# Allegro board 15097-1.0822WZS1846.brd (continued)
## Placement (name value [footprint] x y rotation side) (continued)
R183  -  [0R0402-PAD]  58.24 144.93 90 top
R184  100KR2J-1-GP  [R402H16]  60.24 144.93 90 top
R185  10KR2J-3-GP  [R402H16]  163.33 140.95 0 top
R186  10R2F-L-GP  [R402H14]  160.84 139.06 180 top
R187  0R2J-2-GP  [R402H16]  45.58 137.82 0 top
R188  0R2J-2-GP  [R402H16]  46.62 137.82 0 top
R189  0R2J-2-GP  [R402H16]  47.76 137.82 0 top
R190  0R2J-2-GP  [R402H16]  48.8 137.82 0 top
R191  10R2F-L-GP  [R402H14]  160.85 136.83 180 top
R192  10R2F-L-GP  [R402H14]  160.85 134.89 0 top
R193  NTC-100K-8-GP  [NTC-603H38]  101.98 134.58 270 top
R194  10KR2J-3-GP  [R402H16]  100.1 132.76 90 top
R195  0R0402-PAD-1-GP  [0R0402-PAD]  160.86 132.88 0 top
R196  100KR2J-1-GP  [R402H16]  161.96 130.86 0 top
R197  0R2J-2-GP  [R402H16]  79.51 130.91 270 top
R198  0R0402-PAD-1-GP  [0R0402-PAD]  148.52 130.78 90 top
R199  0R2J-2-GP  [R402H16]  76.69 130.35 90 top
R200  100KR2J-1-GP  [R402H16]  159.82 131.75 180 top
R201  33R2J-2-GP  [R402H16]  88.63 128.62 90 top
R202  0R2J-2-GP  [R402H16]  76.66 129.31 90 top
R203  0R0402-PAD-2-GP  [0R0402-PAD-1]  148.12 129.11 270 top
R204  10KR2J-3-GP  [R402H16]  88.65 127.57 90 top
R205  0R0402-PAD-1-GP  [0R0402-PAD]  152.03 128.65 90 top
R206  0R2J-2-GP  [R402H16]  76.64 128.24 270 top
R207  33R2J-2-GP  [R402H16]  88.65 126.54 90 top
R208  0R2J-2-GP  [R402H16]  76.64 127.03 270 top
R209  10KR2J-3-GP  [R402H16]  88.65 125.47 90 top
R210  10KR2J-3-GP  [R402H16]  81.95 124.33 270 top
R211  10KR2J-3-GP  [R402H16]  76.31 124.26 180 top
R212  0R0402-PAD-2-GP  [0R0402-PAD-1]  88.59 123.08 90 top
R213  20KR2J-L2-GP  [R402H16]  144.16 119.75 0 top
R214  1KR2J-1-GP  [R402H16]  145.46 122.09 0 top
R215  10KR2J-3-GP  [R402H16]  75.6 121.87 0 top
R216  1KR2J-1-GP  [R402H16]  147.03 121.66 270 top
R217  10KR2J-3-GP  [R402H16]  84.89 120.52 0 top
R218  0R0402-PAD-2-GP  [0R0402-PAD-1]  125.64 119.53 180 top
R219  10KR2J-3-GP  [R402H16]  88.53 120.22 90 top
R220  8K2R2J-3-GP  [R402H16]  115.43 120.35 90 top
R221  0R0402-PAD-1-GP  [0R0402-PAD]  140.5 120.35 270 top
R222  1KR2J-1-GP  [R402H16]  96.65 119.08 90 top
R223  10KR2J-3-GP  [R402H16]  77.96 118.67 0 top
R224  0R2J-2-GP  [R402H16]  37.16 118.13 90 top
R225  0R0402-PAD-2-GP  [0R0402-PAD-1]  142.34 117.66 270 top
R226  8K2R2J-3-GP  [R402H16]  122.26 116.77 270 top
R227  10KR2J-3-GP  [R402H16]  139.67 117.25 180 top
R228  20KR2J-L2-GP  [R402H16]  140.75 117.23 180 top
R229  100KR2J-1-GP  [R402H16]  143.86 117.22 0 top
R230  0R0402-PAD-2-GP  [0R0402-PAD-1]  34.21 117.07 270 top
R231  0R2J-2-GP  [R402H16]  36.27 117.07 90 top
R232  10KR2J-3-GP  [R402H16]  99.94 116.33 0 top
R233  0R0402-PAD-1-GP  [0R0402-PAD]  40.48 116.08 90 top
R234  0R0402-PAD-2-GP  [0R0402-PAD-1]  132.35 115.99 0 top
R235  0R0402-PAD-2-GP  [0R0402-PAD-1]  133.39 115.99 0 top
R236  -  [0R0402-PAD]  34.65 114.99 90 top
R237  0R3J-0-U-GP  [R603H22]  127.01 115.5 90 top
R238  1KR2J-1-GP  [R402H16]  146.22 115.38 180 top
R239  10KR2J-3-GP  [R402H16]  94.8 114.83 90 top
R240  10KR2J-3-GP  [R402H16]  81.69 114.81 0 top
R241  10KR2J-3-GP  [R402H16]  83.65 114.81 0 top
R244  0R0402-PAD-1-GP  [0R0402-PAD]  42.82 114.59 180 top
R245  100KR2J-1-GP  [R402H16]  37.3 114.4 270 top
R246  200R2F-L-GP  [R402H16]  77.69 114.05 90 top
R247  2K49R2F-GP  [R402H16]  75.59 114.02 90 top
R248  0R2J-2-GP  [R402H16]  97.9 113.54 270 top
R250  0R2J-2-GP  [R402H16]  121.83 115.52 90 top
R251  0R3J-0-U-GP  [R603H22]  139.76 111.48 180 top
R252  10KR2F-2-GP  [R402H16]  127.39 111.1 270 top
R253  4K99R2F-L-GP  [R402H16]  47.65 111.07 0 top
R254  4K99R2F-L-GP  [R402H16]  48.67 111.07 180 top
R255  10KR2J-3-GP  [R402H16]  97.57 111 270 top
R256  0R0402-PAD-2-GP  [0R0402-PAD-1]  125.33 110.67 0 top
R257  80D6R2F-L-GP  [R402H16]  47.29 109.62 270 top
R258  243R2F-2-GP  [R402H16]  63.7 109.32 90 top
R259  162R2F-GP  [R402H16]  48.8 109.11 180 top
R260  1KR2J-1-GP  [R402H16]  99.45 108.74 90 top
R261  80D6R2F-L-GP  [R402H16]  47.29 108.61 270 top
R262  10KR2J-3-GP  [R402H16]  97.51 108.45 270 top
R263  0R0402-PAD-2-GP  [0R0402-PAD-1]  160.14 108.27 180 top
R264  40D2R2F-GP  [R402H16]  138.47 108.15 270 top
R265  0R0402-PAD-2-GP  [0R0402-PAD-1]  99.09 107.19 0 top
R266  0R2J-2-GP  [R402H16]  138.47 107.11 270 top
R267  4K99R2F-L-GP  [R402H16]  64.31 106.95 0 top
R268  4K99R2F-L-GP  [R402H16]  63.27 106.93 180 top
R269  0R2J-2-GP  [R402H16]  142.95 105.77 180 top
R270  0R2J-2-GP  [R402H16]  144 105.75 180 top
R271  -  [0R0402-PAD]  145.19 105.74 0 top
R272  0R2J-2-GP  [R402H16]  103.31 104.37 90 top
R273  0R2J-2-GP  [R402H16]  103.28 103.26 90 top
R274  10KR2J-3-GP  [R402H16]  104.81 103.12 180 top
R275  0R0402-PAD-1-GP  [0R0402-PAD]  103.28 102.14 90 top
R276  10KR2J-3-GP  [R402H16]  103.28 100.08 270 top
R277  40K2R2F-GP  [R402H16]  97.64 98.8 270 top
R278  100KR2J-1-GP  [R402H16]  100 97.12 180 top
R279  10KR2F-2-GP  [R402H16]  97.7 95.12 90 top
R280  0R2J-2-GP  [R402H16]  102.9 94.74 180 top
R281  10KR2F-2-GP  [R402H16]  97.7 94.11 90 top
R282  10KR2F-2-GP  [R402H16]  97.7 93.09 90 top
R283  4K99R2F-L-GP  [R402H16]  47.73 92.32 180 top
R284  4K99R2F-L-GP  [R402H16]  48.74 92.32 0 top
R285  10KR2F-2-GP  [R402H16]  97.7 92.08 90 top
R286  1K5R3-GP  [R603H22]  167.7 91.29 0 top
R287  4K99R2F-L-GP  [R402H16]  64.15 91.24 0 top
R288  100KR2J-1-GP  [R402H16]  97.7 91.06 90 top
R289  NTC-100K-8-GP  [NTC-603H38]  120.68 90.43 90 top
R290  10KR2F-2-GP  [R402H16]  97.7 90.04 90 top
R291  243R2F-2-GP  [R402H16]  48.31 89.99 270 top
R292  4K99R2F-L-GP  [R402H16]  64.15 89.34 0 top
R293  51R2  [R402]  67.94 89.2 270 top
R295  0R0402-PAD-1-GP  [0R0402-PAD]  124.04 88.06 90 top
R298  10KR2F-2-GP  [R402H16]  90.48 85.55 0 top
R299  10KR2F-2-GP  [R402H16]  91.52 85.55 0 top
R300  10KR2F-2-GP  [R402H16]  93.96 85.27 270 top
R301  42D2R2F-GP  [R402H16]  67.98 85.09 270 top
R304  24K9R2F-L-GP  [R402H16]  88.96 84.94 270 top
R306  0R0402-PAD-1-GP  [0R0402-PAD]  102.79 84.21 0 top
R307  0R2J-2-GP  [R402H16]  104.66 83.62 90 top
R308  10KR2F-2-GP  [R402H16]  88.53 83.46 180 top
R309  33R2J-2-GP  [R402H16]  89.62 83.46 0 top
R310  4K99R2F-L-GP  [R402H16]  90.69 83.46 180 top
R311  33R2J-2-GP  [R402H16]  91.75 83.46 180 top
R312  0R0402-PAD-1-GP  [0R0402-PAD]  98.62 83.45 0 top
R313  10KR2F-2-GP  [R402H16]  93.94 83.03 270 top
R314  10KR2F-2-GP  [R402H16]  82.1 82.83 180 top
R315  0R2J-2-GP  [R402H16]  104.66 82.42 90 top
R316  0R0603-PAD-2-GP-U  [0R0603-PAD-1-U]  170.92 82.37 0 top
R317  39K2R2F-L-GP  [R402H16]  107.58 81.56 90 top
R318  0R5J-5-GP  [R805H24]  113.06 80.19 270 top
R319  10KR2J-3-GP  [R402H16]  170.09 80.01 0 top
R320  8K2R2J-3-GP  [R402H16]  106.81 79.98 0 top
R321  100KR2J-1-GP  [R402H16]  105.72 79.96 180 top
R324  10KR2J-3-GP  [R402H16]  48.06 78.28 180 top
R325  4K7R2J-2-GP  [R402H16]  103.26 80.11 270 top
R326  10KR2J-3-GP  [R402H16]  170.09 77.98 180 top
R327  10KR2J-3-GP  [R402H16]  54.64 77.65 270 top
R328  18K7R2F-GP  [R402H16]  143.31 77.02 180 top
R329  4K7R2J-2-GP  [R402H16]  57.31 76.96 90 top
R330  0R0402-PAD-2-GP  [0R0402-PAD-1]  47.62 76.73 90 top
R331  10KR2J-3-GP  [R402H16]  54.66 76.61 270 top
R332  10KR2J-3-GP  [R402H16]  99.68 76.23 180 top
R333  4K7R2J-2-GP  [R402H16]  64.92 75.77 270 top
R334  10KR2J-3-GP  [R402H16]  51.21 75.74 270 top
R335  2KR2F-3-GP  [R402H16]  147.21 74.81 180 top
R336  10KR2J-3-GP  [R402H16]  64.92 74.73 270 top
R337  10KR2J-3-GP  [R402H16]  135.1 74.1 90 top
R338  -  [0R0402-PAD]  137.93 73.84 270 top
R339  10KR2J-3-GP  [R402H16]  64.93 73.71 90 top
R340  -  [0R0402-PAD]  132.43 73.56 270 top
R341  -  [0R0402-PAD]  119.87 73.08 180 top
R342  -  [0R0402-PAD]  127.22 72.66 0 top
R343  0R2J-2-GP  [R402H16]  132.43 72.52 90 top
R344  100KR2F-L1-GP  [R402H16]  132.12 71 180 top
R345  0R0402-PAD-2-GP  [0R0402-PAD-1]  122.13 70.86 180 top
R347  -  [0R0603-PAD]  145.41 70.48 90 top
R348  10KR2J-3-GP  [R402H16]  139.62 69.19 270 top
R349  100KR2F-L1-GP  [R402H16]  129.67 69.18 90 top
R350  -  [0R0402-PAD]  131.58 69.18 270 top
R351  1KR2J-1-GP  [R402H16]  137.72 69.17 270 top
R352  15KR2F-GP  [R402H16]  133.87 69.03 0 top
R353  -  [0R0402-PAD]  107.53 68.12 90 top
R354  0R2J-2-GP  [R402H16]  137.96 67.94 90 top
R355  0R2J-2-GP  [R402H16]  136.43 67.44 0 top
R356  0R0402-PAD-2-GP  [0R0402-PAD-1]  140.88 66.93 0 top
R357  -  [0R0402-PAD]  109.96 66.13 180 top
R358  0R0402-PAD-1-GP  [0R0402-PAD]  137.96 65.66 270 top
R359  0R0603-PAD-2-GP-U  [0R0603-PAD-1-U]  161.83 65.58 45 top
R360  0R2J-2-GP  [R402H16]  141.51 64.9 90 top
R361  0R2J-2-GP  [R402H16]  137.96 64.52 90 top
R362  0R2J-2-GP  [R402H16]  141.51 63.75 90 top
R363  0R2J-2-GP  [R402H16]  137.96 63.37 270 top
R364  0R2J-2-GP  [R402H16]  112.28 62.71 270 top
R365  0R2J-2-GP  [R402H16]  141.51 62.61 90 top
R366  0R2J-2-GP  [R402H16]  138.08 61.72 90 top
R367  10KR2J-3-GP  [R402H16]  112.28 61.67 90 top
R368  0R2J-2-GP  [R402H16]  141.51 61.47 90 top
R369  33R2J-2-GP  [R402H16]  138.08 60.58 90 top
R370  1KR2J-1-GP  [R402H16]  157.18 60.4 180 top
R371  0R2J-2-GP  [R402H16]  141.51 60.33 90 top
R372  1KR2J-1-GP  [R402H16]  159.04 60.33 180 top
R373  10KR2F-2-GP  [R402H16]  133.59 60.5 0 top
R374  33R2J-2-GP  [R402H16]  138.08 59.44 270 top
R375  0R0603-PAD-2-GP-U  [0R0603-PAD-1-U]  154.39 59.44 90 top
R376  -  [0R0402-PAD]  111.67 59.41 180 top
R377  0R2J-2-GP  [R402H16]  141.51 59.18 90 top
R378  0R0402-PAD-1-GP  [0R0402-PAD]  138.07 58.39 90 top
R379  0R0402-PAD-2-GP  [0R0402-PAD-1]  100.69 57.81 270 top
R380  0R0402-PAD-1-GP  [0R0402-PAD]  135.13 57.33 90 top
R381  0R0402-PAD-2-GP  [0R0402-PAD-1]  100.69 56.67 270 top
R382  47KR2F-GP  [R402H16]  151.04 56.01 0 top
R383  47KR2F-GP  [R402H16]  152.1 56.01 180 top
R384  2K2R2J-2-GP  [R402H16]  154.47 55.75 180 top
R385  0R2J-2-GP  [R402H16]  112.63 54.46 180 top
R386  -  [0R0402-PAD]  111.57 54.84 0 top
R387  20KR2F-L-GP  [R402H16]  165.67 53.82 90 top
R388  0R0402-PAD-2-GP  [0R0402-PAD-1]  151.32 53.04 180 top
R389  5K1R2F-2-GP  [R402H16]  165.82 52.7 270 top
R390  1KR2J-1-GP  [R402H16]  133.88 52.02 270 top
R391  10KR2F-2-GP  [R402H16]  165.82 51.64 270 top
R392  10KR2J-3-GP  [R402H16]  150.86 51.31 90 top
R393  100KR2F-L1-GP  [R402H16]  136.65 50.74 90 top
R394  0R0402-PAD-1-GP  [0R0402-PAD]  134.71 50.72 90 top
R396  0R2J-2-GP  [R402H16]  150.86 50.19 270 top
R397  10KR2J-3-GP  [R402H16]  112.76 49.35 270 top
R399  -  [0R0402-PAD]  133.05 48.99 270 top
R400  0R2J-2-GP  [R402H16]  117.69 48.46 180 top
R401  0R0402-PAD-1-GP  [0R0402-PAD]  118.96 48.46 0 top
R402  0R0402-PAD-2-GP  [0R0402-PAD-1]  120 48.46 180 top
R403  0R0402-PAD-1-GP  [0R0402-PAD]  126.91 48.26 0 top
R404  0R2J-2-GP  [R402H16]  127.92 48.26 0 top
R405  0R2J-2-GP  [R402H16]  125.84 48.25 0 top
R406  2K2R2J-2-GP  [R402H16]  165.79 48.21 90 top
R407  0R2J-2-GP  [R402H16]  112.78 48.08 90 top
R408  0R0402-PAD-1-GP  [0R0402-PAD]  124.72 47.37 0 top
R409  0R5J-5-GP  [R805H24]  58.15 47.05 270 top
R410  10R2F-L-GP  [R402H14]  165.77 46.81 90 top
R411  33R2J-2-GP  [R402H16]  151.45 45.55 90 top
R412  10R2F-L-GP  [R402H14]  165.74 45.42 90 top
R413  100KR2J-1-GP  [R402H16]  66.58 45.14 180 top
R414  33KR2J-3-GP  [R402H16]  148.93 45.14 180 top
R415  -  [0R0402-PAD]  133.49 44.55 270 top
R416  -  [0R0402-PAD]  151.45 44.51 270 top
R417  0R0402-PAD-2-GP  [0R0402-PAD-1]  155.81 42.44 180 top
R418  4K7R2F-GP  [R402H16]  133.78 41.54 0 top
R419  4D3KR2F-GP  [R402H16]  130.71 41.54 180 top
R420  4K7R2F-GP  [R402H16]  131.72 41.54 0 top
R421  4K7R2F-GP  [R402H16]  132.74 41.54 0 top
R422  4K7R2F-GP  [R402H16]  134.9 41.54 0 top
R423  4K7R2F-GP  [R402H16]  128.67 41.08 0 top
R424  0R0603-PAD-2-GP-U  [0R0603-PAD-1-U]  157.64 40.41 90 top
R425  0R1206-PAD-1-GP  [0R1206-PAD-1]  42.15 40.28 270 top
R426  1KR2J-1-GP  [R402H16]  152.81 40.13 270 top
R427  0R0603-PAD-2-GP-U  [0R0603-PAD-1-U]  161.07 39.75 270 top
R428  100KR2J-1-GP  [R402H16]  92.29 39.68 180 top
R429  0R2J-2-GP  [R402H16]  93.79 39.25 90 top
R430  0R0603-PAD-2-GP-U  [0R0603-PAD-1-U]  164.42 38.89 90 top
R431  0R0603-PAD-2-GP-U  [0R0603-PAD-1-U]  161.07 38.48 90 top
R432  0R0603-PAD-2-GP-U  [0R0603-PAD-1-U]  164.4 37.64 270 top
R433  10R3J-3-GP  [R603H22]  155.51 37.41 90 top
R434  10K5R3F-GP  [R603H22]  161.07 37.21 270 top
R435  0R2J-2-GP  [R402H16]  159.16 36.5 0 top
R436  10K5R3F-GP  [R603H22]  164.4 36.3 270 top
R437  0R3J-0-U-GP  [R603H22]  84.93 39.65 270 top
R438  -  [0R0402-PAD]  160.82 35.18 90 top
R439  100KR2J-1-GP  [R402H16]  68.84 34.75 90 top
R440  0R0603-PAD-2-GP-U  [0R0603-PAD-1-U]  163.47 34 0 top
R441  0R0402-PAD-2-GP  [0R0402-PAD-1]  94.78 33.15 180 top
R444  0R0402-PAD-2-GP  [0R0402-PAD-1]  45.52 32.56 0 top
R445  1K5R2J-3-GP  [R402H16]  46.57 32.56 180 top
R446  47R2J-2-GP  [R402H16]  86.29 32.44 90 top
R447  47R2J-2-GP  [R402H16]  84.26 32.41 90 top
R448  1KR2J-1-GP  [R402H16]  30.28 32.16 180 top
R449  0R1206-PAD-1-GP  [0R1206-PAD-1]  41 31.8 270 top
R450  1KR2J-1-GP  [R402H16]  33.69 31.72 180 top
R451  5K6R2F-2-GP  [R402H16]  163.3 31.47 180 top
R452  10KR2J-3-GP  [R402H16]  29.63 30.7 90 top
R453  10KR2F-2-GP  [R402H16]  41.7 30.19 90 top
R454  100KR2J-1-GP  [R402H16]  160.54 30.07 180 top
R455  300KR2F-GP  [R402H16]  38.79 29.72 180 top
R458  1KR2J-1-GP  [R402H16]  30.51 29.16 180 top
R459  4K7R2F-GP  [R402H16]  132.28 28.3 90 top
R460  10KR2J-3-GP  [R402H16]  41.69 28.24 270 top
R461  10KR2F-2-GP  [R402H16]  160.54 28.17 180 top
R462  3K9R2F-GP  [R402H16]  159.47 28.04 180 top
R463  0R0402-PAD-2-GP  [0R0402-PAD-1]  38.13 27.94 90 top
R464  4K7R2F-GP  [R402H16]  132.28 27.18 270 top
R465  4K7R2J-2-GP  [R402H16]  38.13 26.87 90 top
R466  0R0603-PAD-2-GP-U  [0R0603-PAD-1-U]  159.34 26.49 270 top
R467  4K7R2J-2-GP  [R402H16]  38.13 25.73 90 top
R468  0R2J-2-GP  [R402H16]  155.13 25.35 90 top
R469  0R0402-PAD-2-GP  [0R0402-PAD-1]  34.81 25.15 0 top
R470  0R0402-PAD-2-GP  [0R0402-PAD-1]  33.74 25.12 0 top
R471  0R0402-PAD-2-GP  [0R0402-PAD-1]  84.64 25.07 0 top
R472  100KR2J-1-GP  [R402H16]  37.24 24.64 270 top
R473  1KR2J-1-GP  [R402H16]  38.44 23.57 270 top
R474  10KR2J-3-GP  [R402H16]  141.21 22.63 270 top
R475  0R0402-PAD-2-GP  [0R0402-PAD-1]  152.26 22.38 270 top
R476  33R2J-2-GP  [R402H16]  44.53 22.07 180 top
R477  15KR2F-GP  [R402H16]  45.6 22.07 0 top
R478  100KR2J-1-GP  [R402H16]  46.69 22.07 180 top
R479  0R0402-PAD-2-GP  [0R0402-PAD-1]  154.8 21.79 270 top
R480  15KR2F-GP  [R402H16]  31.45 19.84 180 top
R481  10KR2J-3-GP  [R402H16]  38.11 19.53 0 top
R482  1KR2J-1-GP  [R402H16]  31.39 17.95 180 top
R483  1KR2J-1-GP  [R402H16]  135.42 17.86 90 top
R484  10MR3F-GP  [R603H22]  137.77 17.85 90 top
R485  10KR2J-3-GP  [R402H16]  44.79 16.36 180 top
R486  10KR5F-2-GP  [R805H24]  23.83 16 270 top
R487  3D3R3F-GP  [R603H22]  146.59 15.54 180 top
R489  3D3R3F-GP  [R603H22]  146.59 12.73 0 top
R490  10KR2J-3-GP  [R402H16]  138.37 12.41 270 top
R491  10KR2J-3-GP  [R402H16]  29.93 12.27 0 top
R492  75R3F-GP  [R603H22]  63.28 11.94 270 top
R493  0R2J-2-GP  [R402H16]  135.9 11.35 270 top
R494  0R0402-PAD-2-GP  [0R0402-PAD-1]  138.38 11.35 270 top
R495  75R3F-GP  [R603H22]  135.97 10.2 270 top
R496  3D3R3F-GP  [R603H22]  146.59 10.03 180 top
R498  2K49R2F-GP  [R402H16]  39.12 9.8 180 top
R499  8K2R2J-3-GP  [R402H16]  47.2 9.37 90 top
R500  1MR3F-GP  [R603H22]  36.36 9.27 270 top
R501  75R3F-GP  [R603H22]  135.98 8.98 90 top
R502  39K2R2F-L-GP  [R402H16]  45.3 7.98 0 top
R503  75R3F-GP  [R603H22]  136 7.72 90 top
R504  3D3R3F-GP  [R603H22]  146.59 7.21 0 top
R505  0R2J-2-GP  [R402H16]  133.71 6.88 270 top
R506  75R3F-GP  [R603H22]  136 6.43 270 top
R507  10KR2J-3-GP  [R402H16]  129.88 6.22 270 top
R508  10KR2J-3-GP  [R402H16]  131.81 6.22 270 top
R510  10KR2J-3-GP  [R402H16]  41.77 5.82 270 top
R511  0R0402-PAD-2-GP  [0R0402-PAD-1]  89.46 225.14 270 bottom
R512  0R3J-0-U-GP  [R603H22]  102.27 224.71 90 bottom
R513  470R2F-GP  [R402H16]  87.66 224.7 180 bottom
R514  470R2F-GP  [R402H16]  85.35 224.7 180 bottom
R515  10KR2J-3-GP  [R402H16]  83.37 224.67 180 bottom
R516  10KR2J-3-GP  [R402H16]  81.26 226.01 180 bottom
R517  0R0402-PAD-2-GP  [0R0402-PAD-1]  112.94 223.94 270 bottom
R518  0R2J-2-GP  [R402H16]  110.56 223.89 90 bottom
R519  0R3J-0-U-GP  [R603H22]  95.4 223.88 270 bottom
R520  1KR2J-1-GP  [R402H16]  112.94 222.87 270 bottom
R521  0R2J-2-GP  [R402H16]  110.54 222.78 90 bottom
R522  0R0402-PAD-2-GP  [0R0402-PAD-1]  122.09 221.48 90 bottom
R523  0R3J-0-U-GP  [R603H22]  102.72 219.48 90 bottom
R524  470R2F-GP  [R402H16]  79.54 219.33 270 bottom
R525  10KR2J-3-GP  [R402H16]  133.89 219.2 0 bottom
R526  0R2J-2-GP  [R402H16]  87.09 218.85 270 bottom
R527  470R2F-GP  [R402H16]  83.15 218.81 0 bottom
R528  0R0402-PAD-2-GP  [0R0402-PAD-1]  99.03 218.76 90 bottom
R529  0R0402-PAD-2-GP  [0R0402-PAD-1]  107.64 216.9 180 bottom
R530  0R0402-PAD-2-GP  [0R0402-PAD-1]  87.1 216.66 180 bottom
R531  0R0402-PAD-2-GP  [0R0402-PAD-1]  133.89 215.14 0 bottom
R532  1KR2J-1-GP  [R402H16]  26.07 214.21 270 bottom
R533  8K2R2J-3-GP  [R402H16]  128.81 214 0 bottom
R534  39K2R2F-L-GP  [R402H16]  127.8 214 180 bottom
R535  0R3J-0-U-GP  [R603H22]  96.47 213.58 0 bottom
R536  10KR2J-3-GP  [R402H16]  107.96 213.02 180 bottom
R539  0R0402-PAD-2-GP  [0R0402-PAD-1]  66.96 211.58 270 bottom
R540  4K7R2F-GP  [R402H16]  23.39 210.87 0 bottom
R541  1KR2J-1-GP  [R402H16]  28.96 210.44 270 bottom
R542  0R0805-PAD-1-GP-U  [0R0805-PAD-U]  130.08 209.8 180 bottom
R543  100R2J-2-GP  [R402H14]  24.87 208.81 270 bottom
R544  0R0402-PAD-2-GP  [0R0402-PAD-1]  26.83 208.79 270 bottom
R545  0R0402-PAD-2-GP  [0R0402-PAD-1]  68.13 208.79 180 bottom
R546  51R2J-2-GP  [R402H16]  29.63 207.21 90 bottom
R547  10KR2J-3-GP  [R402H16]  99.22 207.01 180 bottom
R548  10KR2J-3-GP  [R402H16]  97.47 207.01 0 bottom
R549  10KR2J-3-GP  [R402H16]  96.2 207.01 180 bottom
R550  10KR2J-3-GP  [R402H16]  95.03 207.01 180 bottom
R551  10KR2J-3-GP  [R402H16]  93.81 207.01 180 bottom
R552  10KR2J-3-GP  [R402H16]  92.36 207.01 0 bottom
R553  10KR2J-3-GP  [R402H16]  91.22 207.01 0 bottom
R554  10KR2J-3-GP  [R402H16]  90.08 207.01 0 bottom
R556  0R0402-PAD-2-GP  [0R0402-PAD-1]  22.2 206.99 270 bottom
R557  10KR2J-3-GP  [R402H16]  100.31 206.98 180 bottom
R558  100KR2F-L1-GP  [R402H16]  68.49 206.5 90 bottom
R559  0R0402-PAD-2-GP  [0R0402-PAD-1]  29.65 206.13 270 bottom
R560  0R0402-PAD-2-GP  [0R0402-PAD-1]  27.09 205.64 0 bottom
R561  0R0402-PAD-2-GP  [0R0402-PAD-1]  22.19 205.75 270 bottom
R563  0R0402-PAD-2-GP  [0R0402-PAD-1]  29.66 205.06 270 bottom
R564  0R0402-PAD-2-GP  [0R0402-PAD-1]  22.19 204.67 270 bottom
R565  51R2J-2-GP  [R402H16]  24.2 204.64 90 bottom
R566  0R2J-2-GP  [R402H16]  68.49 204.47 90 bottom
R567  51R2J-2-GP  [R402H16]  29.67 203.9 90 bottom
R568  10KR2J-3-GP  [R402H16]  67.03 203.71 0 bottom
R569  0R3J-0-U-GP  [R603H22]  162.7 203.68 90 bottom
R570  0R3J-0-U-GP  [R603H22]  156.63 201.89 270 bottom
R571  0R0402-PAD-1-GP  [0R0402-PAD]  76.26 194.59 90 bottom
R572  0R0603-PAD-1-GP-U  [0R0603-PAD-U]  80.68 194.31 0 bottom
R573  0R0402-PAD-1-GP  [0R0402-PAD]  71.62 194.15 270 bottom
R574  -  [0R0805-PAD]  19.65 193.24 0 bottom
R575  -  [0R0805-PAD]  17.59 193.21 0 bottom
R577  1KR2J-1-GP  [R402H16]  28.61 188.72 0 bottom
R578  3K65R2F-1-GP  [R402H16]  137.93 187.86 90 bottom
R580  0R0402-PAD-2-GP  [0R0402-PAD-1]  26.45 186.69 0 bottom
R581  3K65R2F-1-GP  [R402H16]  139.1 185.17 0 bottom
R582  0R0805-PAD-1-GP-U  [0R0805-PAD-U]  88.96 183.59 90 bottom
R583  200R2F-L-GP  [R402H16]  79.92 179.58 180 bottom
R584  200R2F-L-GP  [R402H16]  84.3 179.14 90 bottom
R585  1KR2F-3-GP  [R402H16]  138.79 178.87 0 bottom
R586  1KR2F-3-GP  [R402H16]  139.25 176.11 90 bottom
R587  0R0402-PAD-2-GP  [0R0402-PAD-1]  27.47 172.09 90 bottom
R588  470R2F-GP  [R402H16]  30.26 169.42 90 bottom
R589  105R2F-GP  [R402H16]  93.56 166.6 180 bottom
R590  200R2F-L-GP  [R402H16]  74.93 165.86 90 bottom
R591  105R2F-GP  [R402H16]  89.58 163.2 90 bottom
R592  150R2F-1-GP  [R402H16]  76 162.48 90 bottom
R593  150R2F-1-GP  [R402H16]  73.8 162.44 270 bottom
R594  0R0603-PAD-2-GP-U  [0R0603-PAD-1-U]  87.33 162.28 0 bottom
R595  60D4R2F-GP  [R402H16]  73.03 160.02 90 bottom
R596  0R0603-PAD-1-GP-U  [0R0603-PAD-U]  95.41 157.38 90 bottom
R597  137R2F-GP  [R402H16]  82.7 157.27 180 bottom
R598  0R0805-PAD-1-GP-U  [0R0805-PAD-U]  70.01 157.16 0 bottom
R599  0R3J-0-U-GP  [R603H22]  106.89 155.85 90 bottom
R600  113R2F-GP  [R402H16]  83.12 155.37 180 bottom
R601  0R0805-PAD-1-GP-U  [0R0805-PAD-U]  95.21 155.52 90 bottom
R602  0R3J-0-U-GP  [R603H22]  106.89 154.2 90 bottom
R603  0R0603-PAD-1-GP-U  [0R0603-PAD-U]  93.24 153.69 90 bottom
R604  402R2F-GP  [R402H16]  73.33 153.45 0 bottom
R605  0R0603-PAD-1-GP-U  [0R0603-PAD-U]  71.03 153.37 270 bottom
R606  0R0603-PAD-1-GP-U  [0R0603-PAD-U]  93.24 152.26 90 bottom
R607  0R0603-PAD-1-GP-U  [0R0603-PAD-U]  71.43 152.17 270 bottom
R608  0R0603-PAD-1-GP-U  [0R0603-PAD-U]  73.21 150.9 270 bottom
R609  150R2F-1-GP  [R402H16]  86.87 150.78 0 bottom
R610  3K65R2F-1-GP  [R402H16]  138.98 149.57 180 bottom
R611  0R2J-2-GP  [R402H16]  106.46 148.97 270 bottom
R612  0R2J-2-GP  [R402H16]  106.46 147.83 270 bottom
R613  0R3J-0-U-GP  [R603H22]  94.57 147.47 0 bottom
R614  0R3J-0-U-GP  [R603H22]  96.59 147.46 0 bottom
R615  0R0603-PAD-1-GP-U  [0R0603-PAD-U]  91.59 146.93 90 bottom
R616  0R0603-PAD-1-GP-U  [0R0603-PAD-U]  77.76 146.62 270 bottom
R617  3K65R2F-1-GP  [R402H16]  138.54 146.15 90 bottom
R620  1KR2J-1-GP  [R402H16]  141.13 141.93 180 bottom
R621  -  [0R0402-PAD]  51.19 137.82 180 bottom
R622  -  [0R0402-PAD]  50.15 137.82 180 bottom
R623  -  [0R0402-PAD]  48.8 137.82 180 bottom
R624  -  [0R0402-PAD]  47.76 137.82 180 bottom
R625  -  [0R0402-PAD]  46.62 137.82 180 bottom
R626  -  [0R0402-PAD]  45.58 137.82 180 bottom
R627  0R2J-2-GP  [R402H16]  141.55 135.75 0 bottom
R628  10KR2J-3-GP  [R402H16]  140.27 135.72 180 bottom
R629  10KR2J-3-GP  [R402H16]  127.67 128.42 180 bottom
R630  10KR2J-3-GP  [R402H16]  130.61 128.4 180 bottom
R631  33R2J-2-GP  [R402H16]  93.76 125.99 270 bottom
R632  33R2J-2-GP  [R402H16]  96.45 121.97 180 bottom
R633  10KR2J-3-GP  [R402H16]  44.66 119.93 0 bottom
R634  1KR2F-3-GP  [R402H16]  43.56 119.91 180 bottom
R635  10KR2J-3-GP  [R402H16]  42.46 119.91 180 bottom
R639  330R3J-L-GP  [R603H22]  39.94 108.86 180 bottom
R641  0R0603-PAD-1-GP-U  [0R0603-PAD-U]  76.87 114.3 90 bottom
R642  4K7R2J-2-GP  [R402H16]  33.57 113.89 270 top
R643  243R2F-2-GP  [R402H16]  48.15 112.09 90 bottom
R644  10KR2J-3-GP  [R402H16]  88.7 110.46 0 bottom
R645  4K99R2F-L-GP  [R402H16]  63.73 110.16 270 bottom
R646  4K99R2F-L-GP  [R402H16]  48.74 109.9 180 bottom
R647  4K99R2F-L-GP  [R402H16]  47.73 109.9 0 bottom
R649  10KR2J-3-GP  [R402H16]  44.84 109.19 180 bottom
R651  100R2F-L1-GP-U  [R402H14]  45.91 109.22 180 bottom
R652  4K99R2F-L-GP  [R402H16]  64.19 108.68 180 bottom
R653  10KR2J-3-GP  [R402H16]  94.62 107.43 0 bottom
R654  0R2J-2-GP  [R402H16]  136.38 106.77 180 bottom
R655  1KR2F-3-GP  [R402H16]  42.36 105.52 270 bottom
R656  10KR2J-3-GP  [R402H16]  42.37 104.14 270 bottom
R657  0R0402-PAD-2-GP  [0R0402-PAD-1]  31.53 99.75 270 bottom
R658  12KR2F-L-GP  [R402H16]  31.53 98.73 90 bottom
R659  60D4R2F-GP  [R402H16]  77.55 96.53 0 bottom
R660  10KR2F-2-GP  [R402H16]  95.46 95.9 180 bottom
R661  10KR2F-2-GP  [R402H16]  96.53 95.87 180 bottom
R662  0R0402-PAD-2-GP  [0R0402-PAD-1]  94.01 95.3 180 bottom
R664  100KR2J-1-GP  [R402H16]  31.53 94.11 270 bottom
R665  49K9R2F-L-GP  [R402H16]  96.43 93.68 90 bottom
R666  60D4R2F-GP  [R402H16]  73.54 93.61 0 bottom
R667  10KR2F-2-GP  [R402H16]  96.43 92.63 90 bottom
R668  10KR2J-3-GP  [R402H16]  44.48 92.56 0 bottom
R669  4K99R2F-L-GP  [R402H16]  63.67 92.25 270 bottom
R670  4K99R2F-L-GP  [R402H16]  48.31 91.99 90 bottom
R671  40D2R2F  [R402H16]  76.61 91.33 0 bottom
R672  100KR2J-1-GP  [R402H16]  31.53 91.24 90 bottom
R673  4K99R2F-L-GP  [R402H16]  48.34 90.95 90 bottom
R674  4K99R2F-L-GP  [R402H16]  64.12 90.76 180 bottom
R675  100KR2J-1-GP  [R402H16]  86.32 90.53 270 bottom
R676  100KR2J-1-GP  [R402H16]  31.53 90.17 90 bottom
R677  100KR2J-1-GP  [R402H16]  91.31 90.14 90 bottom
R679  243R2F-2-GP  [R402H16]  63.68 89.28 270 bottom
R680  1KR2J-1-GP  [R402H16]  31.53 89.15 90 bottom
R682  10KR2J-3-GP  [R402H16]  31.54 88.09 90 bottom
R683  80D6R2F-L-GP  [R402H16]  47.34 87.88 90 bottom
R684  162R2F-GP  [R402H16]  48.85 87.44 0 bottom
R685  100KR2J-1-GP  [R402H16]  31.53 87.04 90 bottom
R686  80D6R2F-L-GP  [R402H16]  47.34 86.82 90 bottom
R687  4K7R2J-2-GP  [R402H16]  39.58 86.51 0 bottom
R688  0R0402-PAD-2-GP  [0R0402-PAD-1]  37.37 86.49 0 bottom
R689  0R0402-PAD-2-GP  [0R0402-PAD-1]  36.1 86.49 0 bottom
R690  4K7R2J-2-GP  [R402H16]  35.09 86.49 0 bottom
R691  33R2J-2-GP  [R402H16]  95.66 86.46 180 bottom
R692  10KR2F-2-GP  [R402H16]  96.78 86.03 0 bottom
R693  4K99R2F-L-GP  [R402H16]  85.76 84.86 180 bottom
R696  10KR2F-2-GP  [R402H16]  95.71 83.57 0 bottom
R697  10KR2F-2-GP  [R402H16]  96.74 83.56 0 bottom
R698  0R2J-2-GP  [R402H16]  84.11 83.06 0 bottom
R699  0R2J-2-GP  [R402H16]  82.58 83.06 0 bottom
R700  4K7R2J-2-GP  [R402H16]  42.25 79.43 180 bottom
R701  4K7R2J-2-GP  [R402H16]  30.26 77.29 180 bottom
R702  0R0402-PAD-2-GP  [0R0402-PAD-1]  44.89 76.5 90 bottom
R703  20KR2F-L-GP  [R402H16]  139.91 75.86 90 bottom
R704  0R0402-PAD-2-GP  [0R0402-PAD-1]  45.15 75.45 90 bottom
R705  1KR2J-1-GP  [R402H16]  141.54 74.34 0 bottom
R706  330KR2J-L1-GP  [R402H16]  140.44 74.34 180 bottom
R707  0R0402-PAD-2-GP  [0R0402-PAD-1]  49.33 74.32 90 bottom
R708  10KR2F-2-GP  [R402H16]  133.54 74.23 180 bottom
R709  0R0402-PAD-1-GP  [0R0402-PAD]  132.49 74.23 0 bottom
R710  0R2J-2-GP  [R402H16]  44.79 74.27 90 bottom
R711  200KR2J-L1-GP  [R402H16]  131.03 72.8 90 bottom
R712  1KR2J-1-GP  [R402H16]  132.93 72.78 270 bottom
R713  -  [0R0603-PAD]  122.45 71.32 90 bottom
R714  33R2J-2-GP  [R402H16]  47.87 71.43 90 bottom
R715  -  [0R0603-PAD]  138.35 57.2 270 top
R716  10KR2F-2-GP  [R402H16]  134.1 70.95 180 bottom
R717  33R2J-2-GP  [R402H16]  47.87 70.39 90 bottom
R718  -  [0R0402-PAD]  124.8 70.37 270 bottom
R719  0R2J-2-GP  [R402H16]  134.12 68.95 180 bottom
R720  10KR2F-2-GP  [R402H16]  128.36 67.3 180 bottom
R721  100KR2F-L1-GP  [R402H16]  127.3 67.29 0 bottom
R722  0R2J-2-GP  [R402H16]  116.09 66.1 90 bottom
R723  -  [0R0402-PAD]  116.09 65.04 90 bottom
R724  -  [0R0402-PAD]  123.92 64.53 270 bottom
R725  33R2J-2-GP  [R402H16]  33.35 63.65 90 bottom
R726  -  [0R0603-PAD]  123.55 63.36 270 bottom
R727  160KR2F-GP  [R402H16]  48.19 63.27 270 bottom
R728  2K2R2J-2-GP  [R402H16]  135.42 61.99 270 bottom
R729  1KR2J-1-GP  [R402H16]  135.42 60.96 90 bottom
R730  24K9R2F-L-GP  [R402H16]  130.65 60.94 90 bottom
R731  0R2J-2-GP  [R402H16]  33.35 60.57 90 bottom
R732  24K9R2F-L-GP  [R402H16]  128.69 60.38 0 bottom
R733  24K9R2F-L-GP  [R402H16]  127.5 60.37 0 bottom
R734  0R0402-PAD-2-GP  [0R0402-PAD-1]  135.42 59.94 270 bottom
R735  0R2J-2-GP  [R402H16]  33.36 59.51 90 bottom
R736  2D2R3-1-U-GP  [R603H22]  114.98 58.79 180 bottom
R737  100KR2F-L1-GP  [R402H16]  133.34 59.03 90 top
R738  0R0402-PAD-1-GP  [0R0402-PAD]  122.72 57.35 0 bottom
R739  24K9R2F-L-GP  [R402H16]  127.1 57.03 90 bottom
R742  100KR2F-L1-GP  [R402H16]  125.04 55.39 180 bottom
R743  -  [0R0402-PAD]  118.35 55.38 0 bottom
R744  1MR3F-GP  [R603H22]  150.73 54.13 0 bottom
R745  10KR2J-3-GP  [R402H16]  125.05 53.47 180 bottom
R746  100KR2F-L1-GP  [R402H16]  151.09 52.25 270 bottom
R747  0R0603-PAD-2-GP-U  [0R0603-PAD-1-U]  160.69 51.18 0 bottom
R748  1KR2J-1-GP  [R402H16]  153.61 49.03 90 bottom
R749  -  [0R0402-PAD]  154.9 46.99 270 bottom
R750  0R2J-2-GP  [R402H16]  154.9 45.9 270 bottom
R751  0R5J-5-GP  [R805H24]  59.85 43.81 90 bottom
R753  0R5J-5-GP  [R805H24]  59.85 41.78 90 bottom
R754  4K7R2F-GP  [R402H16]  133.78 41.54 0 bottom
R755  4K7R2F-GP  [R402H16]  132.74 41.54 0 bottom
R756  4K7R2F-GP  [R402H16]  131.72 41.54 0 bottom
R757  -  [0R0603-PAD]  152.75 41.45 270 bottom
R758  0R5J-5-GP  [R805H24]  59.85 39.75 90 bottom
R759  4K7R2J-2-GP  [R402H16]  153.96 39.09 270 bottom
R760  10KR2J-3-GP  [R402H16]  152.03 39.09 90 bottom
R761  D33R6F-GP  [R1206H26]  41.94 38.48 270 bottom
R762  0R5J-5-GP  [R805H24]  59.85 37.72 90 bottom
R764  D33R6F-GP  [R1206H26]  41.94 36.2 270 bottom
R766  200R5J-GP  [R805H24]  34.75 35.18 180 bottom
R767  0R5J-5-GP  [R805H24]  38.01 35.15 180 bottom
R768  0R0402-PAD-2-GP  [0R0402-PAD-1]  27.92 32.82 270 bottom
R769  0R0402-PAD-2-GP  [0R0402-PAD-1]  26.02 32.36 270 bottom
R770  0R0402-PAD-2-GP  [0R0402-PAD-1]  27.92 31.6 270 bottom
R771  10R2F-L-GP  [R402H14]  41.23 32.03 180 bottom
R772  0R0402-PAD-2-GP  [0R0402-PAD-1]  26.02 30.96 270 bottom
R774  33R2J-2-GP  [R402H16]  27.36 28.17 270 bottom
R775  300KR2F-GP  [R402H16]  38.2 27.5 270 bottom
R776  33R2J-2-GP  [R402H16]  27.36 27.13 270 bottom
R778  10KR2F-2-GP  [R402H16]  38.13 26.42 270 bottom
R779  33R2J-2-GP  [R402H16]  27.36 26.06 270 bottom
R780  1KR2J-1-GP  [R402H16]  24.52 26.04 270 bottom
R781  100R2F-L1-GP-U  [R402H14]  31.94 25.7 180 bottom
R782  4K7R2J-2-GP  [R402H16]  39.66 25.02 0 bottom
R783  -  [0R0402-PAD]  24.52 24.99 90 bottom
R784  10KR2F-2-GP  [R402H16]  29.12 24.96 270 bottom
R785  1KR2F-3-GP  [R402H16]  36.02 24.33 180 bottom
R786  100KR2F-L1-GP  [R402H16]  34.07 24.31 180 bottom
R787  33R2J-2-GP  [R402H16]  29.12 23.93 90 bottom
R788  2K2R2J-2-GP  [R402H16]  42.49 27.25 270 bottom
R789  10KR2J-3-GP  [R402H16]  40.09 23.5 90 bottom
R790  100KR2J-1-GP  [R402H16]  38.13 23.5 90 bottom
R791  10KR2J-3-GP  [R402H16]  129.9 22.86 0 bottom
R792  10KR2F-2-GP  [R402H16]  30.23 22.3 180 bottom
R793  0R0402-PAD-1-GP  [0R0402-PAD]  44.66 20.98 90 bottom
R794  1KR2J-1-GP  [R402H16]  30.23 19.91 0 bottom
R795  180R3F-GP  [R603H22]  123.47 19.18 270 bottom
R796  36R3F-GP  [R603H22]  126.27 19.18 270 bottom
R797  2KR2F-3-GP  [R402H16]  35.48 18.65 90 bottom
R798  10KR2J-3-GP  [R402H16]  28.71 13.44 90 bottom
R799  10KR2J-3-GP  [R402H16]  26.42 13.44 0 bottom
R800  8K2R2J-3-GP  [R402H16]  28.68 12.37 270 bottom
R801  10KR5F-2-GP  [R805H24]  25.56 10.97 270 bottom
R802  10KR2J-3-GP  [R402H16]  43.98 10.44 270 bottom
R803  10KR2J-3-GP  [R402H16]  37.05 9.55 180 bottom
R804  10KR2J-3-GP  [R402H16]  42.07 9.45 270 bottom
R805  10KR2J-3-GP  [R402H16]  40.09 8.33 270 bottom
R806  8K2R2J-3-GP  [R402H16]  46.41 6.07 180 bottom
R807  0R2J-2-GP  [R402H16]  45.4 6.07 180 bottom
R808  0R3J-0-U-GP  [R603H22]  24.68 5.69 270 bottom
R809  0R2J-2-GP  [R402H16]  156.47 49.53 180 bottom
R810  -  [0R0402-PAD]  53.08 75.54 90 bottom
R811  0R0805-PAD-1-GP-U  [0R0805-PAD-U]  41.03 19.86 90 bottom
R812  0R2J-2-GP  [R402H16]  51.6 76.72 0 bottom
R814  1KR2J-1-GP  [R402H16]  160.73 134.62 0 bottom
R815  10KR2J-3-GP  [R402H16]  165.18 140.7 270 bottom
R816  200R2F-L-GP  [R402H16]  85.75 85.26 90 top
R1701  100KR2F-L1-GP  [R402H16]  54.21 150.7 0 top
R1702  0R2J-2-GP  [R402H16]  53.17 150.7 180 top
R1703  0R2J-2-GP  [R402H16]  61.63 146.84 0 top
R1801  10KR2F-2-GP  [R402H16]  86.49 192.7 0 top
R1802  10KR2F-2-GP  [R402H16]  85.43 192.7 0 top
R1803  10KR2J-3-GP  [R402H16]  139.81 85.55 90 top
R1804  4K7R2J-2-GP  [R402H16]  134.25 66.01 180 bottom
R1805  100KR2J-1-GP  [R402H16]  75.04 127.81 180 top
R1806  0R2J-2-GP  [R402H16]  151.77 171.86 180 top
R1807  0R2J-2-GP  [R402H16]  151.77 173.81 0 top
R1808  2K2R2J-2-GP  [R402H16]  133.21 66.01 0 bottom
R2001  4K7R2F-GP  [R402H16]  160.69 158.47 0 top
R2002  10KR2J-3-GP  [R402H16]  160.71 156.41 0 top
R2401  0R2J-2-GP  [R402H16]  142.48 41.27 180 top
R2402  0R2J-2-GP  [R402H16]  125.23 74.3 180 bottom
R2403  10KR2J-3-GP  [R402H16]  119.84 71.09 180 top
R4501  100KR2J-1-GP  [R402H16]  141.59 82.33 0 top
R5501  100KR2F-L1-GP  [R402H16]  34.68 116.02 90 top
R5502  10KR2J-3-GP  [R402H16]  121.29 67.77 270 bottom
R9201  0R2J-2-GP  [R402H16]  139.25 45.64 270 top
R9202  0R2J-2-GP  [R402H16]  143.06 56.54 180 top
RJ1  RJ45-8P-199-GP  [23-01120-2A03-A]  76.92 21.04 180 top
RN1  SRN0J-6-GP  [SMD-ARES4H20]  33.41 216.34 0 top
RN2  SRN10KJ-5-GP  [ARES2H18]  96.6 200.91 90 top
RN4  SRN10KJ-5-GP  [ARES2H18]  88.02 192.66 180 top
RN5  SRN10KJ-5-GP  [ARES2H18]  86.37 187.12 0 top
RN6  SRN10KJ-5-GP  [ARES2H18]  88.4 187.12 0 top
RN7  SRN10KJ-5-GP  [ARES2H18]  60.21 179.45 270 top
RN8  SRN10KJ-5-GP  [ARES2H18]  56.17 174.62 270 top
RN9  SRN2K2J-1-GP  [ARES2H16]  141.03 78.54 270 top
RN11  SRN0J-6-GP  [SMD-ARES4H20]  111.89 68.67 0 top
RN12  SRN4K7J-8-GP  [SMD-ARES4H18]  136.69 54.36 90 top
RN13  SRN4K7J-8-GP  [SMD-ARES4H18]  136.69 52.32 90 top
RN14  SRN0J-6-GP  [SMD-ARES4H20]  132.9 46.99 90 top
RN15  SRN100F-1-GP  [SMD-ARES4H20]  54.9 200.79 180 bottom
RN16  SRN1KJ-7-GP  [SMD-ARES4H18]  14.03 222.31 90 top
RN17  SRN1KJ-7-GP  [SMD-ARES4H18]  6.87 221.08 270 top
RN18  SRN100F-1-GP  [SMD-ARES4H20]  24.69 206.29 270 bottom
RN19  SRN100KJ-6-GP  [SMD-ARES4]  100.15 85.19 180 top
RN20  SRN2K2J-1-GP  [ARES2H16]  97.34 85.42 90 top
RN21  SRN10KJ-5-GP  [ARES2H18]  105.82 212.47 180 bottom
RN22  SRN10KJ-5-GP  [ARES2H18]  86.65 114.76 90 top
RN23  SRN20KJ-1-GP  [SMD-ARES4H20]  147.05 35.79 90 bottom
RN24  SRN4K7J-8-GP  [SMD-ARES4H18]  23.27 28.19 180 bottom
RN25  SRN2K2J-1-GP  [ARES2H16]  135.37 29.04 0 top
RN30  SRN100KJ-6-GP  [SMD-ARES4]  98.04 88.51 270 top
RN32  SRN2K2J-1-GP  [ARES2H16]  165.9 50.04 90 top
RN34  SRN4K7J-8-GP  [SMD-ARES4H18]  140.1 7.42 90 top
RN35  SRN4K7J-8-GP  [SMD-ARES4H18]  45.77 78.89 270 top
RN36  SRN2K2J-1-GP  [ARES2H16]  130.08 28.19 0 top
RN37  SRN10KJ-5-GP  [ARES2H18]  32.12 32.6 0 top
RN38  SRN100KJ-6-GP  [SMD-ARES4]  90.8 88.63 90 bottom
RN39  SRN10KJ-5-GP  [ARES2H18]  27.15 15.97 270 top
RN40  SRN10KJ-5-GP  [ARES2H18]  115.68 56.42 90 bottom
RN41  SRN4K7J-8-GP  [SMD-ARES4H18]  31.76 84.63 90 bottom
RV1  P4500SCLHLRP-GP  [TVS5436-1121H105]  65.32 19.24 0 top
SATAP1  CLX-CON5-18-GP-U  [CI2505P1H00-LF-U]  12 195 270 top
SPK1  JWT-CON6-20-GP  [A1501WV0-6PS-5E]  149.7 13 270 top
SRCON1  SKT-SPI8P-GP-U1  [SKT-SOIC8-092117H235]  96.02 125.57 90 top
SSUSB1  SKT-USB11-112-GP-U  [SKT-USB11-138165-1]  176.12 116.84 90 top
SSUSB2  SKT-USB11-112-GP-U  [SKT-USB11-138165-1]  176.12 95.34 90 top
TC1  ST100U6D3VBM-7GP  [CT3528H79]  19.85 194.56 90 top
TC2  E100U16VM-47-GP  [ECAP-100D6D3H237]  167.61 105.58 0 top
TC3  E100U16VM-108-GP-U  [ECAP-100D6D3H237]  92.06 22.83 0 top
TC4  ST330U2D5VDM-9GP  [CT7343H75]  131.1 204.09 270 bottom
TOUCH1  ENT-CON5-GP  [3703K-Q05N-11L]  24.7 8.5 270 top
TP1  -  [TPAD28]  107.24 223.47 0 top
TP2  -  [TPAD28]  105.85 223.36 0 top
TP3  -  [TPAD28]  124.58 222.19 0 top
TP4  -  [TPAD28]  105.95 222.06 0 top
TP5  -  [TPAD28]  107.22 222.06 0 top
TP6  -  [TPAD28]  105.95 220.47 0 top
TP7  -  [TPAD28]  107.22 220.47 0 top
TP8  -  [TPAD28]  124.12 215.28 0 top
TP9  -  [TPAD28]  121.32 215.26 0 top
TP10  -  [TPAD28]  122.59 215.26 0 top
TP11  -  [TPAD28]  121.32 214 0 top
TP12  -  [TPAD28]  122.59 214 0 top
TP13  -  [TPAD28]  121.32 212.72 0 top
TP14  -  [TPAD28]  122.59 212.72 0 top
TP15  -  [TPAD28]  121.32 211.46 0 top
TP16  -  [TPAD28]  122.59 211.46 0 top
TP17  -  [TPAD28]  121.32 210.19 0 top
TP18  -  [TPAD28]  122.59 210.19 0 top
TP19  -  [TPAD28]  104.68 209.93 0 top
TP20  -  [TPAD28]  105.95 209.93 0 top
TP21  -  [TPAD28]  107.22 209.93 0 top
TP22  -  [TPAD28]  121.32 208.91 0 top
TP23  -  [TPAD28]  122.59 208.91 0 top
TP24  -  [TPAD28]  104.68 208.03 0 top
TP25  -  [TPAD28]  105.95 208.03 0 top
TP26  -  [TPAD28]  107.22 208.03 0 top
TP27  -  [TPAD28]  121.32 207.65 0 top
TP28  -  [TPAD28]  122.59 207.65 0 top
TP29  -  [TPAD28]  90.51 201.23 0 top
TP30  -  [TPAD28]  68.64 182.19 0 top
TP31  -  [TPAD28]  49.03 174.92 90 top
TP32  -  [TPAD28]  61.71 174.73 0 top
TP33  -  [TPAD28]  158.49 173.01 180 top
TP34  -  [TPAD28]  68.94 169.8 90 top
TP35  -  [TPAD28]  68.92 168.48 90 top
TP36  -  [TPAD28]  68.19 158.26 0 top
TP37  -  [TPAD28]  68.39 153.42 0 top
TP38  -  [TPAD28]  68.37 152.18 0 top
TP39  -  [TPAD28]  74.49 146.65 0 top
TP40  -  [TPAD28]  75.73 146.65 0 top
TP41  -  [TPAD28]  74.51 145.41 0 top
TP42  -  [TPAD28]  75.73 145.41 0 top
TP43  -  [TPAD28]  146.23 129.44 0 top
TP44  -  [TPAD28]  129.9 115.32 90 top
TP45  -  [TPAD28]  131.15 115.42 90 top
TP46  -  [TPAD28]  96.22 114.86 180 bottom
TP47  -  [TPAD28]  97.57 114.43 180 bottom
TP48  -  [TPAD28]  126.58 109.91 90 top
TP49  -  [TPAD28]  127.85 109.78 90 top
TP50  -  [TPAD28]  125.33 108.86 0 top
TP51  -  [TPAD28]  127.31 88.9 0 top
TP52  -  [TPAD28]  113.49 59.36 0 top
TP53  -  [TPAD28]  157.72 34.95 180 top
TP54  -  [TPAD28]  91.34 224.94 0 bottom
TP55  -  [TPAD28]  97.06 218.92 0 bottom
TP56  -  [TPAD28]  91.1 217.64 180 bottom
TP57  -  [TPAD28]  91.08 216.02 180 bottom
TP58  -  [TPAD28]  87.11 215.02 0 bottom
TP59  -  [TPAD28]  91.08 214.75 180 bottom
TP60  -  [TPAD28]  92.46 213.86 180 bottom
TP61  -  [TPAD28]  72.42 178.69 180 bottom
TP62  -  [TPAD28]  73.69 178.56 180 bottom
TP63  -  [TPAD28]  76.23 177.04 180 bottom
TP64  -  [TPAD28]  74.73 176.05 180 bottom
TP65  -  [TPAD28]  75.98 175.51 180 bottom
TP66  -  [TPAD28]  73.76 174.7 180 bottom
TP68  -  [TPAD28]  74.64 172.32 90 bottom
TP69  -  [TPAD28]  73.39 172.29 90 bottom
TP70  -  [TPAD28]  74.73 153.71 180 bottom
TP71  -  [TPAD28]  74.67 152.45 180 bottom
TP72  -  [TPAD28]  81.92 150.9 180 bottom
TP73  -  [TPAD28]  76.78 149.92 180 bottom
TP74  -  [TPAD28]  75.55 149.91 180 bottom
TP75  -  [TPAD28]  80.52 149.67 180 bottom
TP76  -  [TPAD28]  90.02 109.57 180 bottom
TP77  -  [TPAD24]  73.77 91.26 180 bottom
TP78  -  [TPAD28]  88.17 89.53 180 bottom
TP79  -  [TPAD28]  95.64 88.9 180 bottom
TP80  -  [TPAD28]  96.96 87.76 180 bottom
TP81  -  [TPAD28]  93 87.6 180 bottom
TP82  -  [TPAD28]  84.11 81.41 180 bottom
TP83  -  [TPAD28]  82.58 81.41 180 bottom
TP84  -  [TPAD28]  135.15 19.56 90 bottom
TP85  -  [TPAD28]  135.05 16.91 90 bottom
TR1  FILTER-4P-137-GP-U  [L125100-4P-4H28]  106.54 205.51 180 top
TR2  FILTER-4P-137-GP-U  [L125100-4P-4H28]  162.66 191.02 270 top
TR3  FILTER-4P-137-GP-U  [L125100-4P-4H28]  164.31 112.84 180 top
TR4  FILTER-4P-137-GP-U  [L125100-4P-4H28]  164.32 110.54 180 top
TR5  FILTER-4P-120-GP  [L125100-4P-1H28]  126.41 38.87 0 top
TR6  FILTER-4P-120-GP  [L125100-4P-1H28]  126.41 36.71 0 top
TR7  FILTER-4P-120-GP  [L125100-4P-1H28]  126.41 34.43 0 top
TR8  FILTER-4P-120-GP  [L125100-4P-1H28]  126.41 32.27 0 top
TR9  FILTER-4P-137-GP-U  [L125100-4P-4H28]  112.35 26.09 0 top
TR10  FILTER-4P-137-GP-U  [L125100-4P-4H28]  112.35 23.85 0 top
TR11  FILTER-4P-137-GP-U  [L125100-4P-4H28]  31.55 11.46 90 top
U1  KLMBG4GEND-B031-GP  [BGA153G115130-1H40]  93.91 216.57 180 top
U2  NCT3956Y-GP  [DFN10G3-G265175H32]  81.06 128.37 270 top
U3  MX25U6473FM2I-10G-GP  [SOIC8-1H86]  96.02 125.57 270 top
U4  AZ1045-04F-R7G-GP  [DFN10G2510H26]  168.92 118.24 270 top
U5  NL17SZ08DFT2G-GP  [SC70-5H44]  97.54 116.1 0 top
U6  TVLST2304BD0-GP  [SOT-6H58]  168.3 111.51 90 top
U7  NPCT650JAAYX-GP  [QFN32G5-G3D6H32]  132.39 110.72 90 top
U8  AP22802AW5-7-GP  [SOT-23-5H58]  161.31 105.31 90 top
U9  AZ1045-04F-R7G-GP  [DFN10G2510H26]  169.2 96.27 270 top
U11  NCP81172MNTXG-GP-U  [LFQFN24G4-G2D9H40]  127.54 82.04 0 top
U12  NCT7718W-GP  [MSOP8-1H44]  145.93 79.17 0 top
U13  G2129TL1U-GP  [SC70-6H44]  137.39 71.74 90 top
U14  NPCE985PB1DX-GP-U  [LQFP128H63]  123.25 59.13 90 top
U15  TPS22966DPUR-GP  [SON14J3020-G2610H34]  105.01 57.18 90 top
U16  ALC3661-CG-GP  [QFN48J6-G465H40]  159.55 48.77 90 top
U17  TC7SZ08FU-2-GP  [SC70-5H44]  136.2 47.02 180 top
U18  AZ1045-04F-R7G-GP  [DFN10G2510H26]  123.3 40.64 270 top
U19  AZ1045-04F-R7G-GP  [DFN10G2510H26]  123.3 37.11 90 top
U20  PS8407ATQFN40GTR2-A1-GP  [QFN40J5-G3D65H32]  132.74 35.57 270 top
U21  AZ1045-04F-R7G-GP  [DFN10G2510H26]  123.3 33.58 270 top
U22  TPA3131D2RHBR-GP-U  [QFN32-G3D55H40]  155.35 30.61 270 top
U23  AP22802AW5-7-GP  [SOT-23-5H58]  92.62 29.59 0 top
U24  AZ1215-04S-R7G-GP  [SOT-6H58]  78.19 28.96 270 top
U25  TVLST2304BD0-GP  [SOT-6H58]  107.98 25.1 90 top
U26  RTL8111G-CGT-1-GP-U2  [QFN32J4-G2D85H36]  36.61 14.99 270 top
U27  2N7002K-2-GP  [SOT23DGS2D4H44]  136.51 14.82 270 top
U28  AZ1215-04S-R7G-GP  [SOT-6H58]  46.64 12.95 270 top
U29  TPS22966DPUR-GP  [SON14J3020-G2610H34]  102.27 222.1 90 bottom
U31  RTD2136S-CG-GP  [QFN48J6-G4D55H40]  37.78 94.5 270 bottom
U32  MX25L1006EMI-10G-GP  [SOIC8H69]  91.47 84.15 270 bottom
U33  M24C64-WMN6TP-2-GP  [SOIC8H69]  38.01 81.79 180 bottom
U34  BQ24727RGRR-1-GP  [QFN20G3D5-G2D15H40]  48.42 57.78 180 bottom
U35  OZ554ALN-B-0-TR-GP  [QFN20-G2D1H32]  32.93 29.72 90 bottom
U36  AZ1117CR-ADJTRG1-GP-U  [SOT-89-4541-3PH63]  122.72 21.34 180 bottom
U37  AZ1215-04S-R7G-GP  [SOT-6H58]  46.64 12.95 270 bottom
U38  NCT3521U-2-GP  [SOT-6-1H58]  37.34 109.58 180 bottom
U39  AP22802AW5-7-GP  [SOT-23-5H58]  164.49 143.68 0 bottom
UHS1  AUDIO-JK500-GP  [2SJ3082-038111F]  176.5 75.29 90 top
UR1  330R2F-GP  [R402H16]  83.52 25.04 0 top
UR2  330R2F-GP  [R402H16]  69.5 24.71 0 top
UR3  330R2F-GP  [R402H16]  70.65 24.71 0 top
UR4  330R2F-GP  [R402H16]  85.76 25.08 0 top
USB3  SKT-USB6-174-GP  [SKT-USB6-135063]  98.35 37.03 90 top
USB4  SKT-USB6-174-GP  [SKT-USB6-135063]  98.35 14.03 90 top
VRAM1  H5TQ1G63DFR-11C-GP  [BGA96D075130H48]  56 111 0 top
VRAM2  H5TQ1G63DFR-11C-GP  [BGA96D075130H48]  56 88.24 180 top
VRAM3  H5TQ1G63DFR-11C-GP  [BGA96D075130H48]  56 111 180 bottom
VRAM4  H5TQ1G63DFR-11C-GP  [BGA96D075130H48]  56 88.24 0 bottom
WEBCM1  JWT-CON8-4-GP  [A1251WR0-8PS-5E]  160.12 201.1 180 top
X1  XTAL-32D768KHZ-67-GP  [SMD49-6914-0403H56]  72.32 191.29 90 top
X2  XTAL-19D2MHZ-3-GP  [OSC-3225-4P-4H32]  62.3 157.98 90 top
X3  XTAL-27MHZ-85-GP-U  [OSC-3225-4P-4H30]  85.13 82.01 0 top
X4  XTAL-25MHZ-181-GP  [OSC-3225-4P-4H36]  36.36 6.86 0 top
XDP1  STC-CONN60A-GP-U1  [QSH-030-01-FDAK]  26.04 212.24 90 top
XF1  XFORM-12P-48-GP  [XFORM12A127097H91]  55.91 11.94 90 top
XF2  XFORM-12P-48-GP  [XFORM12A127097H91]  55.91 11.94 270 bottom

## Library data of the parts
AFTP1 = AFTE14P-75: tolerance: ZZ.AFT14.101
BAT2 = 51202-00901-W01-U: tolerance: 020.F0592.0009
BT1 = AAA-BAT-034-K01: tolerance: 62.70010.031
C1 C2 C7 C9 C14 C26 C38-C41 C46 C47 C56 C57 C61 C62 C70 C73 C74 C78 C80 C82 C84 C87 C88 C103 C104 C110-C112 C122 C126 C133 C134 C136-C138 C143 C148 C153 C157 C160 C162 C163 C169 C170 C195 C196 C203 C204 C218-C220 C224 C225 C240 C241 C245 C250 C251 C260 C274 C275 C289 C290 C311 C321 C329 C332 C338 C339 C341 C342 C344 C353-C355 C371 C372 C374 C377 C397 C402-C404 C410 C412 C416 C417 C419 C427-C429 C434-C436 C438 C442-C445 C448 C449 C459 C460 C463 C468 C470 C472 C474 C476 C477 C483 C486 C495 C505 C508 C510 C521 C522 C526-C529 C531 C533-C535 C537 C539 C543 C547 C568 PC37 PC47 PC57 PC58 PC78 PC93 PC98 PC110 PC111 PC119 PC148 = C402H22: tolerance: 78.10421.2FLDL
C3 C12 C13 C17 C96 C100 C132 C164 C166 C291-C293 C314 C316 C335-C337 C348 C349 C351 C360 C361 C363 C366 C370 C400 C447 C455 C484 C487 = C603H36: tolerance: 78.10610.5BLDL
C4 C142 C207 C208 C262 C481 = C805H54: tolerance: 78.10623.51L
C5 C10 = C603H36: tolerance: 78.10424.2BL
C6 C93 C180 C216 C553-C563 EC2901 PC68 PC91 PC100 PC101 PC109 PC114 PC118 PC121 PC127 PC128 PC180-PC182 PC189 PC193 = C603H35: tolerance: 78.10424.2BLDL
C8 C175 C181 C458 C500 C506 PC17 PC19 PC61 PC66 PC86 PC103-PC105 PC124 PC129 PC131 PC139 PC170 PC173 PC174 PC177 PC178 PC190 PC196 PC197 PCB1 PCT1 = C805H58: tolerance: 78.10622.51LDL
C11 C140 C149 C230 C249 C473 C542 = C603H36: tolerance: 78.22523.5BLDL
C15 C59 C72 C75 C90 C145-C147 C151 C152 C261 C362 C365 C396 C401 C461 C479 C480 C501 C519 C546 C565 PC21 PC23 PC25 PC34 PC35 PC48 PC49 PC64 PC67 PC69-PC71 PC77 PC79 PC82 PC83 = C805H50: tolerance: 78.10623.51LDL
C16 C71 C178 C197 C200 C368 C373 C385 C387 C426 C433 C485 C532 C536 PC26 PC81 PC99 PC106 PC125 = C603H36: tolerance: 078.10524.05BD
C18 C168 PC80 = C402H22: tolerance: 78.10134.1FL
C19 C27-C29 C35 C52 C65-C67 C83 C85 C86 C95 C99 C101 C113 C117-C119 C156 C159 C167 C189 C235 C242 C248 C265-C268 C280 C282 C283 C286 C287 C294-C301 C304-C309 C312 C313 C315 C317-C320 C322-C328 C330 C331 C333 C334 C340 C345-C347 C369 C379-C384 C389 C392 C424 C432 C437 C439 C454 C462 C513 C564 C569 PC5 PC6 PC33 PC43 PC45 PC62 PC72 PC73 PC89 PC115 PC117 PC120 PC134 PC155 PC157 PC160 PC194 = C402H22: tolerance: 78.10523.5FLDL
C20 C22 C24 C25 C55 C68 C69 C79 C108 C276 C350 C367 C391 C394 C411 PC31 PC32 PC36 PC44 PC46 PC54-PC56 PC84 PC145 PC149-PC154 PC156 PC158 PC159 PC161-PC169 PC171 PC195 = C805H54: tolerance: 78.22610.51LDL
C21 C23 = C402H22: tolerance: 078.2R774.01FD
C30 = C402H22: tolerance: 78.10324.2FLDL; signal model: Graser_C30
C31 = C402H22: tolerance: 78.10324.2FLDL; signal model: Graser_C31
C32 = C402H22: tolerance: 78.47034.1FL
C33 = C402H22: tolerance: 78.10324.2FLDL; signal model: Graser_C33
C34 = C402H22: tolerance: 78.10324.2FLDL; signal model: Graser_C34
C36 C37 = C402H22: tolerance: 78.3R374.1FLDL
C42-C45 C356-C359 = C402H22: tolerance: 078.22423.05FD
C48 C49 C352 C375 C376 C378 C386 C388 C390 C393 C398 C399 C406-C409 C413 C414 C420-C422 C425 C430 C440 C446 C456 C548 PC94 PC113 PC185 = C603H36: tolerance: 78.47520.5BLDL
C50 = C402H22: tolerance: 78.10324.2FLDL; signal model: Graser_C50
C51 = C402H22: tolerance: 78.10324.2FLDL; signal model: Graser_C51
C53 = C402H22: tolerance: 78.10324.2FLDL; signal model: Graser_C53
C54 = C402H22: tolerance: 78.10324.2FLDL; signal model: Graser_C54
C58 C89 C121 C123 C124 C131 C161 C184 C185 C187 C469 C471 C498 C516 EC8601-EC8604 PC28 PC63 PC97 = C402H22: tolerance: 78.10134.1FLDL
C60 = C402H22: tolerance: 78.10421.2FLDL; signal model: Graser_C60
C63 = C402H22: tolerance: 78.10421.2FLDL; signal model: Graser_C63
C64 C81 C91 C190 C206 C209 C285 C343 C489 C511 C514 C524 = C402H22: tolerance: 78.10421.2FL
C76 C171 C198 C205 C221 C465 C490 C491 C503 C504 PC3 PC132 PC179 = C402H22: tolerance: 78.10324.2FLDL
C77 C450 = C402H22: tolerance: 78.10322.2FLLL
C92 = C402H22: tolerance: 78.10421.2FLDL; signal model: Graser_C92
C94 = C402H22: tolerance: 78.10421.2FLDL; signal model: Graser_C94
C114 C115 C227 = C402H22: tolerance: 78.15034.1FLDL
C116 = C402H22: tolerance: 78.10421.2FLLL
C120 = C402H22: tolerance: 78.10322.2FLDL
C125 PC102 PC140 = C402H22: tolerance: 78.22224.2FLDL
C127 PC8 PC10 PC14 PC16 PC30 PC42 PC51 PC122 PC126 PC184 = C402H22: tolerance: 78.47124.2FLDL
C128-C130 PC191 PC192 = C603H36: tolerance: 78.10422.2BLDL
C135 C281 C467 = C402H22: tolerance: 78.10423.2FL
C139 = C402H22: tolerance: 78.10423.2FLDL
C141 = C402H22: tolerance: 78.22124.2FL
C144 C150 C236 C238 = C402H22: tolerance: 78.10520.5FLDL
C155 = C402H22: tolerance: 78.10422.5FL
C158 PC24 = C402H22: tolerance: 78.22034.1FL
C165 C488 = C603H38: tolerance: 78.10610.5BL
C172 PC7 PC96 = C402H22: tolerance: 78.33034.1FLDL
C173 PC137 = C402H22: tolerance: 78.10224.2FL
C174 = C402H22: tolerance: 78.10421.2FLDL; signal model: Graser_C174
C176 = C402H22: tolerance: 78.10421.2FLDL; signal model: Graser_C176
C177 = C402H22: tolerance: 78.10421.2FLDL; signal model: Graser_C177
C179 = C402H22: tolerance: 78.10421.2FLDL; signal model: Graser_C179
C182 = C402H22: tolerance: 78.10421.2FLDL; signal model: Graser_C182
C183 C193 C199 C210 = C603H36: tolerance: 78.22422.2BLDL
C186 = C402H22: tolerance: 78.10421.2FLDL; signal model: Graser_C186
C188 = C402H22: tolerance: 78.10421.2FLDL; signal model: Graser_C188
C191 C194 C215 C217 = C603H36: tolerance: 78.27324.2BLDL
C192 = C402H22: tolerance: 78.10421.2FLDL; signal model: Graser_C192
C201 C202 = C402H22: tolerance: 78.10422.5FLLL
C211-C214 = C603H36: tolerance: 78.68421.5BL
C222 C223 C228 C231 C237 C239 C475 C478 C502 C507 C549-C552 EC1 EC2 PC13 PC20 PC60 PC65 PC87 PC107 PC108 PC133 PC138 PC142 PC143 PCT2 = C402H22: tolerance: 78.10224.2FLDL
C226 = C402H22: tolerance: 78.12034.1FLDL
C229 C232 = C402H22: tolerance: 78.10034.1FL
C233 C234 C244 C246 C451-C453 C457 C482 C517 C544 = C402H22: tolerance: 78.10523.5FL
C243 C247 = C402H22: tolerance: 078.47510.05FD
C252-C259 C263 C264 C269-C273 C277-C279 C284 C288 C302 C303 C310 = C603H40: tolerance: 78.22610.5BLDL
C364 = C402H22: tolerance: 78.22321.2FLDL
C395 C405 = C805H54: tolerance: 78.47610.51LDL
C415 = C402H22: tolerance: 78.10421.2FLDL; signal model: Graser_C415
C418 = C402H22: tolerance: 78.10421.2FLDL; signal model: Graser_C418
C423 = C402H22: tolerance: 78.10421.2FLDL; signal model: Graser_C423
C431 = C402H22: tolerance: 78.10421.2FLDL; signal model: Graser_C431
C464 = C603H36: tolerance: 78.22523.5BL
C466 = C402H22: tolerance: 78.10520.5FL
C492 = C1206H71: tolerance: 78.10525.22LLL
C493 C496 C497 C499 = C1206H75: tolerance: 078.10525.022D
C494 = C603H36: tolerance: 78.10492.4BLLL
C509 = C603H36: tolerance: 78.10521.5BL
C512 = C402H22: tolerance: 78.27034.1FLLL
C515 PC186 = C603H36: tolerance: 78.47422.5BLDL
C520 C523 C530 C541 = C603H36: tolerance: 78.47520.5BL
C525 C538 C540 C545 = C603H36: tolerance: 78.10324.2BL
CMCLR2 EC_DEBUG1 = A2541WV0-1EX2PA-6T: tolerance: 21.60909.102
CONVT1 = CI1410M1HRL-NH: tolerance: 20.F2266.010
CPU1 = BGA1296M3124H56: tolerance: 071.APOLL.000U
D1 D6 D8 = SOD323AKH38: tolerance: 83.00355.D1F
D2-D4 = SOT23-2D4-312H48: tolerance: 75.00054.R7D
D5 = SOT23-2D4-312H48: tolerance: 75.00099.F7D
D7 = SOT-23-9H44: tolerance: 75.00040.07D
D9 = SOD523AKH28: tolerance: 83.02015.0AF
D10 = D4724AKH44: tolerance: 83.3R010.C8M
DCIN1 = 2DC3115-000111F: tolerance: 022.10015.0311
DCIN2 = 88314-077N: tolerance: 20.F1498.007
DIMM1 = AS0A621-J4R6-7H-U: tolerance: 62.10024.S21
EC518 = C1808H87: tolerance: 078.1013N.014D
EMC1-EMC4 = SPR6024H64: tolerance: 34.41L50.001
F1 = POLYSW-2114H30: tolerance: 069.50003.0001
F2 = FUSE-1608H22: tolerance: 69.43001.441
F3 F4 F7 F8 = POLYSW-2114H30: tolerance: 069.50001.0031
F5 = FUSE-3216H28: tolerance: 69.41501.051
FANC3 = HF1804H: tolerance: 021.D0086.0104
GPU1 = BGA595M23H83: tolerance: 071.0N16S.0A0U
H1-H5 = HOLE237R158: tolerance: ZZ.0HOLE.011
H6 H9 = GEN8D5X8R5X4D5-8-F-A: tolerance: ZZ.00PAD.BV1
H7 = GEN315R138-8-F-A-1: tolerance: ZZ.00PAD.BU1
H10 = GEN315R178-8-F-A-1: tolerance: ZZ.00PAD.BR1
H11 = GEN315R138-8-F-A-2-S: tolerance: ZZ.00PAD.HK1
HDD1 ODD1 = 15-02070-5A61-A: tolerance: 020.80244.0007
HDMI1 = SKT-HDMI22-150077: tolerance: 062.10012.0121
HDMI2 = LVDFH-02004-TP00: tolerance: 20.F2139.020
HS6 = STF256R109H99: tolerance: 34.3NH01.001
